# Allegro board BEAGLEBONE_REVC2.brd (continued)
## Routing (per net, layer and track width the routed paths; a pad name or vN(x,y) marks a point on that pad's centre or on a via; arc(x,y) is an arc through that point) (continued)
PHY_VDDCR: length 4.3
  TOP w0.254: U15.6 26.79,29.33 27.16,28.96 v1(27.18,28.96)
  BOTTOM w0.381: C125.1 28.13,30.54 C124.1 28.07,29.84 v1(27.18,28.96)
PHY_XTAL1: length 6.9
  TOP w0.121: Y4.1 26.29,26.54 v1(26.29,27.81)
  BOTTOM w0.121: R140.2 25.75,25.53 25.88,25.65 25.88,26.42 26,26.54 C132.1 ; C132.1 26.7,26.54 26.83,26.42 26.83,25.65 26.96,25.53 R199.1 ; C132.1 26.29,26.61 v1(26.29,27.81)
PHY_XTAL2: length 4.8
  TOP w0.121: U15.4 25.78,29.21 25.85,29.14 25.85,28.77 25.4,28.32 v1(25.4,27.81)
  BOTTOM w0.121: v1(25.4,27.81) R140.1 R144.1
PHYX: length 5.1
  TOP w0.121: Y4.2 23.18,26.48 v1(23.18,27.81)
  BOTTOM w0.121: R144.2 23.75,25.53 23.62,25.65 23.62,26.42 23.5,26.54 C131.1 v1(23.18,27.81)
PLLFILT: length 2.6
  TOP w0.121: C145.1 16.95,40.32 17.91,41.27 U11.25
PMIC_INT: length 17.7
  TOP w0.121: v1(40.51,27.05) 41.02,27.05 42.26,28.29 U5.B18
  LYR3 w0.133: v1(29.21,23.81) 29.72,24.32 29.72,25.02 29.97,25.27 34.42,25.27 v1(34.92,24.77) 35.18,24.77 35.69,25.27 37.97,25.27 38.61,25.91 39.12,25.91 40.26,27.05 v1(40.51,27.05)
  BOTTOM w0.121: R28.2 v1(34.92,24.77) ; v1(29.21,23.81) R10.2
PMIC_INT_PU: length 4.6
  TOP w0.121: v1(34.92,27.3) 34.51,27.72 33.66,27.72 33.53,27.59 33.53,26.41 33.66,26.28 U14.7
  BOTTOM w0.121: R28.1 v1(34.92,27.3)
PMIC_INT_SRC: length 17.5
  TOP w0.121: 30.61,26.29 29.69,25.37 29.69,21.68 v1(30.16,21.21) ; 30.61,26.29 31.54,26.29 U14.2 ; 30.61,26.29 30.61,26.67 30.72,26.78 U14.1 ; U2.45 24.4,20.08 24.51,20.19 24.51,20.83 v1(24.38,20.95)
  LYR3 w0.133: v1(24.38,20.95) 25.15,21.72 29.65,21.72 v1(30.16,21.21)
  BOTTOM w0.121: R10.1 R203.2 v1(30.16,21.21)
PMIC_PGOOD: length 35
  TOP w0.121: v1(44.73,27.89) U5.B15 ; v1(29.72,13.46) 29.1,14.08 29.1,14.57 28.96,14.71 U2.26
  LYR3 w0.121: v1(44.73,27.89) 44.33,27.49 43.76,27.49
  LYR3 w0.133: v1(29.21,24.77) 29.21,25.15 29.59,25.53 37.72,25.53 38.35,26.16 38.81,26.16 40.13,27.49 42.15,27.49 42.16,27.5 42.5,27.5 42.5,27.49 43.76,27.49
  LYR4 w0.133: v1(29.72,13.46) 30.63,14.38 30.63,24.99 30.35,25.27 29.72,25.27 v1(29.21,24.77)
  BOTTOM w0.121: v1(29.21,24.77) R20.1 C25.1
PMIC_POWR_EN: length 48.1
  TOP w0.121: v1(19.18,15.75) 21.13,15.75 21.37,15.51 U2.9 ; v1(52.73,28.69) U5.C6
  LYR3 w0.133: v1(19.18,15.75) 20.7,17.27 27.94,17.27 28.57,16.64 31.11,16.64 35.56,21.08 39.62,21.08 39.88,21.34 43.94,21.34 44.2,21.08 52.58,21.08 v1(52.7,21.21)
  LYR4 w0.133: v1(52.7,21.21) 52.32,21.59 52.32,28.28 v1(52.73,28.69)
PWR_BUT: length 13.8
  TOP w0.121: v1(29.72,12.64) 28.47,13.88 U2.25
  LYR4 w0.133: P9.9 28.7,3.05 28.7,11.62 v1(29.72,12.64)
PWR_LED: length 21.2
  TOP w0.121: v1(21.46,20.32) 22.33,19.46 U2.1
  BOTTOM w0.121: R6.1 5.4,17.34 5.84,17.78 17.78,17.78 18.8,18.8 18.8,20.32 19.3,20.83 20.95,20.83 v1(21.46,20.32)
PWR_LEDR: length 4
  TOP w0.121: v1(5.59,15.56) D1.2 4.64,17.02 TP14.1
  BOTTOM w0.121: R6.2 5.27,16.32 5.59,16 v1(5.59,15.56)
RBIAS: length 2.7
  TOP w0.121: v1(22.23,29.53) 22.86,30.16 22.86,30.48 23.01,30.63 U15.32
  BOTTOM w0.121: v1(22.23,29.53) 21.46,29.53
RCLKIN: length 9
  TOP w0.121: U15.5 26.29,29.21 26.29,29.21 v1(26.29,28.96) 26.71,28.54 27.35,28.54 27.39,28.57 v1(29.21,28.57)
  BOTTOM w0.121: R199.2 27.3,27.94 v1(26.29,28.96) ; v1(29.21,28.57) 29.69,29.05 30.45,29.05 R200.2
REFCLKO: length 5.2
  TOP w0.121: R209.2 v1(30.1,28.57) 29.59,29.08 27.69,29.08 27.29,29.48 U15.7
  BOTTOM w0.121: R209.2 v1(30.1,28.57)
REMU_RSTN: length 61.5
  TOP w0.121: U16.1 31.1,42.56 30.86,42.8 v1(30.86,43.18)
  LYR3 w0.133: v1(36.2,13.97) 38.86,13.97 40.01,15.11 v1(52.32,15.11)
  LYR4 w0.133: v1(30.86,43.18) 33.02,41.02 33.02,39.12 32.77,38.86 32.77,37.08 32,36.32 32,28.57 32.64,27.94 34.04,27.94 34.42,27.56 34.42,27.05 35.81,25.65 35.81,21.46 35.05,20.7 35.05,15.11 v1(36.2,13.97)
  BOTTOM w0.121: v1(52.32,15.11) 53.47,13.97 54.99,13.97 55.12,14.1 R172.2 58.55,14.61 59.82,15.88 R182.1
RESETN: length 3.8
  TOP w0.121: U11.17 21.46,44.57 22.23,45.34 22.23,45.85 20.95,45.85
RMII1_COL: length 23.4
  TOP w0.121: v1(43.93,32.69) U5.H16 ; R207.1 32.07,35.24 v1(32.64,35.81)
  LYR3 w0.133: v1(43.93,32.69) 43.47,33.15 39.75,33.15 39.62,33.27 38.48,33.27 v1(37.97,32.77)
  BOTTOM w0.121: v1(32.64,35.81) 30.83,35.81 30.61,35.59 30.61,35.28 30.83,35.05 34.29,35.05 34.54,35.31 34.54,36.07 34.8,36.32 35.43,36.32 36.2,35.56 36.2,33.02 36.96,32.26 36.96,31.88 37.21,31.62 37.72,31.62 37.97,31.88 v1(37.97,32.77)
RMII1_CRS_DV: length 23.1
  TOP w0.121: v1(33.66,32.38) 33.66,33.02 32.89,33.78 32.45,33.78 R139.1 ; v1(36.45,32) 36.45,33.02 36.7,33.27 41.31,33.27 41.53,33.49 43.13,33.49 U5.H17
  LYR3 w0.133: v1(33.66,32.38) 34.54,32.38 35.18,33.02 35.69,33.02 35.81,32.89 35.81,32 35.69,31.88 34.29,31.88 34.16,31.75 34.16,31.37 34.29,31.24 37.97,31.24 38.1,31.37 38.1,31.88 37.97,32 v1(36.45,32)
RMII1_REFCLK: length 20.8
  TOP w0.121: R201.2 37.21,31.37 v1(37.21,30.48) ; R209.1 v1(32.64,28.57)
  LYR3 w0.133: v1(37.21,30.48) 36.58,29.84 33.78,29.84 33.66,29.72 33.66,29.46 33.78,29.34 36.58,29.34 36.7,29.21 36.7,28.96 36.58,28.83 34.29,28.83 34.16,28.7 34.16,28.45 34.29,28.32 36.58,28.32 36.7,28.19 36.7,27.94 36.58,27.81 33.4,27.81 v1(32.64,28.57)
  BOTTOM w0.121: v1(32.64,28.57) 32.64,28.83 R200.1
RMII1_RXCLK: length 20.2
  TOP w0.121: v1(37.97,35.81) 38.73,35.81 39.24,36.32 40.77,36.32 41.64,35.45 42.69,35.45 U5.L18
  LYR4 w0.133: v1(33.66,28.57) 34.8,29.72 34.8,35.18 34.92,35.31 35.18,35.31 35.31,35.18 35.31,34.16 35.43,34.04 35.81,34.04 35.94,34.16 35.94,35.18 36.07,35.31 37.47,35.31 v1(37.97,35.81)
  BOTTOM w0.121: R136.1 32.38,28.13 33.21,28.13 v1(33.66,28.57)
RMII1_RXD0: length 23.3
  TOP w0.121: U5.M16 43.93,36.69 v1(43.13,36.69) ; v1(33.66,35.81) 33.15,35.31 33.15,34.04 34.29,32.89 34.29,32.13 34.04,31.88 32.45,31.88 R135.1
  LYR3 w0.133: v1(43.13,36.69) 42.72,37.1 41.91,37.1 41.78,36.97 41.78,36.45 41.66,36.32 38.73,36.32 38.61,36.45 38.61,36.7 38.73,36.83 39.88,36.83 40.01,36.96 40.01,37.21 39.88,37.34 36.07,37.34 35.94,37.21 35.94,36.45 35.81,36.32 34.16,36.32 v1(33.66,35.81)
RMII1_RXD1: length 23.3
  TOP w0.121: U5.L15 v1(44.73,35.09) ; R132.1 32.83,31.43 33.27,30.99 33.91,30.99 34.16,30.73 34.16,28.83 34.29,28.7 34.54,28.7 34.67,28.83 34.67,33.91 34.29,34.29 v1(33.66,34.29)
  LYR3 w0.121: 43.56,34.69 44.09,34.69 44.49,35.09 v1(44.73,35.09)
  LYR3 w0.133: 43.56,34.69 43.55,34.7 34.06,34.7 v1(33.66,34.29)
RMII1_RXD2: length 23.4
  TOP w0.121: R153.1 v1(32.64,30.48) ; v1(44.73,35.89) U5.L16
  LYR4 w0.133: v1(32.64,30.48) 33.15,30.99 33.15,38.35 33.27,38.48 36.32,38.48 v1(37.97,36.83)
  BOTTOM w0.121: v1(44.73,35.89) U5.L16 43.76,35.49 43.18,34.91 43.18,34.67 42.93,34.42 41.02,34.42 39.12,36.32 38.48,36.32 v1(37.97,36.83)
RMII1_RXD3: length 23.1
  TOP w0.121: U5.L17 43.53,35.49 43.13,35.09 41.4,35.09 41.19,35.31 37.72,35.31 v1(37.21,35.81) ; R205.1 v1(32.64,29.53)
  LYR4 w0.133: v1(37.21,35.81) 36.07,35.81 35.94,35.94 35.94,37.34 35.81,37.47 35.43,37.47 35.31,37.34 35.31,36.45 35.18,36.32 34.92,36.32 34.8,36.45 34.8,37.34 34.67,37.47 34.29,37.47 34.16,37.34 34.16,30.1 33.59,29.53 v1(32.64,29.53)
RMII1_RXDV: length 26.4
  TOP w0.121: R208.1 20.45,35.56 20.7,35.81 v1(21.34,35.81) ; U5.J17 v1(43.93,34.29)
  LYR3 w0.133: v1(30.1,35.81) 31.11,34.8 32.77,34.8 33.15,34.42 33.15,34.16 33.53,33.78 34.04,33.78 34.29,34.04 40.01,34.04 40.16,33.88 42.77,33.88 43.18,34.29 v1(43.93,34.29)
  LYR4 w0.133: v1(21.34,35.81) 21.84,36.32 29.59,36.32 v1(30.1,35.81)
RMII1_RXERR: length 23.3
  TOP w0.121: v1(44.73,34.29) U5.J15 ; R137.1 v1(32.64,33.34)
  LYR3 w0.121: v1(44.73,34.29) 44.33,33.89 43.54,33.89
  LYR3 w0.133: v1(32.64,33.34) 30.92,33.34 30.48,33.78 29.08,33.78 28.83,34.04 28.83,34.8 29.08,35.05 30.23,35.05 31.5,33.78 33.02,33.78 33.4,33.4 34.16,33.4 34.54,33.78 39.88,33.78 40.01,33.65 43.3,33.65 43.54,33.89
RMII1_TXCLK: length 23.4
  TOP w0.121: R206.1 31.94,37.02 v1(31.75,37.21) ; v1(35.18,37.97) 35.18,37.21 37.44,34.95 41.01,34.95 41.27,34.69 U5.K18
  LYR3 w0.133: v1(31.75,37.21) 31.11,37.21 30.99,37.08 30.99,36.7 31.11,36.58 35.43,36.58 35.56,36.7 35.56,36.96 35.43,37.08 32.38,37.08 32.26,37.21 32.26,37.44 32.38,37.57 34.77,37.57 v1(35.18,37.97)
RMII1_TXD0: length 28
  TOP w0.121: v1(25.02,35.81) 25.28,35.55 U15.22 ; U5.K17 43.13,34.29 41.15,34.29 40.73,34.71 37.3,34.71 34.42,37.59 v1(34.42,37.97)
  LYR3 w0.133: v1(34.42,37.97) 33.78,38.61 23.37,38.61 23.11,38.35 23.11,36.58 23.24,36.45 24.89,36.45 25.02,36.32 v1(25.02,35.81)
RMII1_TXD1: length 28.7
  TOP w0.121: v1(24.26,35.81) 24.38,35.81 24.78,35.41 U15.23 ; v1(43.93,35.09) U5.K16
  LYR3 w0.133: v1(24.26,35.81) 24.26,35.05 24.38,34.92 25.34,34.92 25.46,35.05 25.46,36.96 25.34,37.08 24.26,37.08 24.13,37.21 24.13,37.72 24.26,37.85 26.42,37.85 27.69,36.58 29.97,36.58 31.5,35.05 43.89,35.05 v1(43.93,35.09)
RMII1_TXD2: length 29.1
  TOP w0.121: U15.24 24.28,35.15 23.81,35.62 23.81,36 24.13,36.32 26.29,36.32 26.48,36.51 29.97,36.51 30.1,36.64 v1(30.1,37.21) ; v1(45.53,35.09) U5.K15
  LYR3 w0.121: 43.62,35.49 45.13,35.49 45.53,35.09 v1(45.53,35.09)
  LYR3 w0.133: v1(30.1,37.21) 30.1,36.83 31.62,35.31 38.35,35.31 38.48,35.43 38.48,35.81 38.61,35.94 38.86,35.94 38.99,35.81 38.99,35.43 39.12,35.31 39.37,35.31 39.5,35.43 39.5,35.81 39.62,35.94 39.88,35.94 40.01,35.81 40.01,35.43 40.13,35.31 41.02,35.31 41.15,35.43 41.15,35.81 41.27,35.94 41.53,35.94 41.66,35.81 41.66,35.43 41.78,35.31 42.04,35.31 42.16,35.43 42.16,35.56 42.29,35.69 42.55,35.69 42.67,35.56 42.67,35.43 42.8,35.31 43.43,35.31 43.62,35.49
RMII1_TXD3: length 28.4
  TOP w0.121: U5.J18 41.15,33.89 41.04,33.78 39.88,33.78 39.37,34.29 37.34,34.29 v1(33.66,37.97) ; U15.25 23.24,34.14 22.92,34.45 22.92,36 23.24,36.32 23.5,36.32 24.51,37.34 27.48,37.34 27.56,37.26 27.56,37.16 27.48,37.08 26.11,37.08 26.04,37.01 26.04,36.84 26.11,36.77 28.89,36.77 v1(29.34,37.21)
  LYR3 w0.133: v1(29.34,37.21) 30.1,37.97 v1(33.66,37.97)
RMII1_TXEN: length 29
  TOP w0.121: U15.21 25.78,35.69 v1(25.91,35.81) ; v1(43.93,33.49) U5.J16
  LYR3 w0.133: v1(43.93,33.49) 43.82,33.38 39.85,33.38 39.72,33.51 34.78,33.51 34.16,32.89 27.3,32.89 26.42,33.78 23.11,33.78 22.99,33.91 22.99,34.29 23.11,34.42 26.42,34.42 26.54,34.54 26.54,34.8 26.42,34.92 26.04,34.92 25.91,35.05 v1(25.91,35.81)
RSVD3: length 2.6
  TOP w0.121: 23.5,45.85 23.5,45.34 22.46,44.3 U11.15
RTC_PORZ: length 30
  TOP w0.121: U5.B5 v1(53.53,27.89)
  LYR3 w0.133: v1(31.11,23.81) 33.34,23.81 33.91,23.24 35.81,23.24 36.73,24.16 38.89,24.16 39.5,24.77 52.45,24.77 53.53,25.84 v1(53.53,27.89)
  BOTTOM w0.121: 31.59,25.53 31.59,24.29 v1(31.11,23.81) R143.2 ; 31.59,25.53 R141.1 ; 31.59,25.53 R18.1
RTCK: length 2.8
  BOTTOM w0.121: R178.2 P7.9
RXD0/MODE0: length 8.4
  TOP w0.121: R135.2 v1(30.1,32.38) 30.1,32.13 29.6,31.63 U15.11
  LYR3 w0.133: v1(32.64,32.38) v1(30.1,32.38)
  BOTTOM w0.121: R198.1 33.91,32.89 33.15,32.89 v1(32.64,32.38) ; v1(30.1,32.38) R135.2
RXD1/MODE1: length 7.6
  TOP w0.121: U15.10 29.8,31.13 v1(30.1,31.43) R132.2
  LYR3 w0.133: v1(33.66,31.43) v1(30.1,31.43)
  BOTTOM w0.121: R5.1 v1(33.66,31.43) ; v1(30.1,31.43) R132.2
RXD2/RMIISEL: length 7.2
  TOP w0.121: U15.9 29.06,30.63 29.21,30.48 v1(30.1,30.48) R153.2 31.4,30 33.18,30 v1(33.66,30.48)
  BOTTOM w0.121: R153.2 v1(30.1,30.48) ; R212.1 v1(33.66,30.48)
RXD3/PHYAD2: length 10.4
  TOP w0.121: U15.8 27.79,29.46 27.91,29.34 29.91,29.34 v1(30.1,29.53) R205.2
  BOTTOM w0.121: R213.1 35.43,28.92 35.31,29.05 34.54,29.05 34.42,29.18 R214.1 33.94,30 30.26,30 30.1,29.84 v1(30.1,29.53)
RXDV: length 2.9
  TOP w0.121: U15.26 23.13,33.64 22.67,34.1 22.67,34.48 22.1,35.05 21.46,35.05
RXER/PHYAD0: length 7.6
  TOP w0.121: R137.2 v1(30.1,33.34) 30.1,33.02 29.97,32.89 29.47,32.89 29.21,32.64 U15.13
  BOTTOM w0.121: R126.2 33.21,33.34 32.73,33.81 31.4,33.81 R137.2 v1(30.1,33.34)
RXN: length 20.3
  TOP w0.095: P10.2 17.14,33.97 17.02,34.1 16.13,34.1 16,33.97 16,32.53 16.52,32 17.78,32 18.52,32.74 18.52,33.39 19.19,34.06 20.18,34.06 21.08,33.16 21.08,31.62 21.61,31.1 21.89,31.1 v1(22.23,31.43) 22.29,31.5 22.85,31.5 22.99,31.63 U15.30
  BOTTOM w0.095: 21.46,31.43 v1(22.23,31.43)
  BOTTOM w0.121: P10.2 C127.1
RXP: length 17.8
  TOP w0.095: U15.31 22.97,31.13 22.89,31.22 22.63,31.22 22.48,31.06 22.48,30.73 v1(22.23,30.48) 21.89,30.82 21.49,30.82 20.8,31.51 20.8,33.05 20.07,33.78 19.3,33.78 18.8,33.27 18.8,32.62 17.9,31.72 16.41,31.72 15.72,32.41 15.72,34.06 15.49,34.29 P10.1
  BOTTOM w0.095: 21.46,30.48 v1(22.23,30.48)
  BOTTOM w0.121: P10.1 C126.1
SD_CD: length 14.8
  LYR3 w0.133: v1(71.63,24.64) 72.14,25.15 72.39,25.15 v1(73.91,26.67)
  BOTTOM w0.121: R197.1 R196.1 70.99,22.23 71.63,22.86 v1(71.63,24.64) ; v1(73.91,26.67) 73.15,27.43 73.15,30.73 71.97,31.92 P4.11
SPI1_CS0: length 27.9
  TOP w0.121: v1(47.13,28.69) U5.C12
  LYR4 w0.133: v1(47.13,28.69) 47.13,28.18 48.01,27.3 48.01,22.99 47.12,22.1 47.12,21.72 49.15,19.68 49.15,17.4 51.05,15.49 51.05,7.62 52.7,5.97 P9.28
SPI1_D0: length 31.7
  TOP w0.121: 55.24,1.91 53.98,3.17 53.98,5.21 53.34,5.84 51.82,5.84 v1(50.67,6.99) ; v1(46.33,27.89) U5.B13
  LYR4 w0.133: v1(46.33,27.89) 46.99,27.23 46.99,23.5 46.35,22.86 46.35,22.1 48.9,19.56 48.9,17.27 50.67,15.49 v1(50.67,6.99)
SPI1_D1: length 29.9
  TOP w0.121: v1(47.13,29.49) U5.D12
  LYR4 w0.121: v1(47.13,29.49) 47.53,29.09 47.53,28.42
  LYR4 w0.133: 55.24,4.45 55.24,5.71 53.34,7.62 52.32,7.62 51.44,8.51 51.44,15.49 49.4,17.53 49.4,19.81 48.13,21.08 48.13,22.23 48.51,22.61 48.51,27.43 47.53,28.42
SPI1_SCLK: length 33.4
  TOP w0.121: v1(46.33,27.09) U5.A13
  LYR4 w0.133: v1(46.33,27.09) 46.33,26.54 46.08,26.29 46.08,22 48.64,19.43 48.64,10.54 49.28,9.91 49.28,7.49 v1(49.78,6.99)
  BOTTOM w0.121: P9.31 56.64,3.05 52.07,3.05 51.44,3.68 51.44,5.33 v1(49.78,6.99)
SYS_5V: length 134.5
  TOP w0.203: 21.59,16.13 21.81,15.91 U2.8 ; 21.59,16.13 v1(21.46,16.13) ; 21.59,16.13 21.77,16.31 U2.7
  TOP w0.381: v1(14.42,45.85) 13.14,45.85 FB4.2
  TOP w0.508: C133.1 69.87,14.63 75.27,14.63 v1(75.57,14.93)
  LYR3 w0.508: 27.3,5.71 67.94,5.71 74.8,12.57 74.8,14.16 v1(75.57,14.93)
  LYR3 w0.762: P9.8 27.3,5.71 23.11,9.91 19.68,9.91 v1(18.8,10.79)
  LYR4 w0.381: v1(14.42,45.85) 13.14,45.85 11.43,44.13 11.43,41.4 14.99,37.85 17.91,37.85 20.32,35.43 20.32,22.86 19.05,21.59 19.05,19.56 20.32,18.29 20.32,16.13
  LYR4 w0.762: v1(21.46,16.13) 20.32,16.13 20.32,14.73 18.8,13.21 v1(18.8,11.56) v1(18.8,10.79)
  BOTTOM w0.381: v1(18.8,10.79) v1(18.8,11.56) 18.29,11.56 18.03,11.3 18.03,10.79 ; v1(18.8,10.79) 18.03,10.79 ; v1(18.8,10.79) 18.8,10.16 R3.2 18.03,10.16 18.03,10.79 ; U9.2 75.89,14.28 75.56,14.61 75.56,14.92 v1(75.57,14.93) U9.3 ; v1(14.42,45.85) 18.41,45.85
  BOTTOM w0.762: P9.7 P9.8
SYS_RESETN: length 81.4
  TOP w0.121: U15.19 v1(26.79,35.81) ; U5.A10 49.13,27.03 48.76,26.66 48.76,26.03 46.86,24.13 v1(46.86,22.61) ; v1(10.29,41.59) 10.16,41.47 R23.2 R27.1
  LYR3 w0.133: v1(31.11,20.45) 31.6,20.93 31.6,21.47 31.85,21.72 32.26,21.72 32.77,21.21 34.04,21.21 34.54,21.72 36.7,21.72 37.08,21.34 39.5,21.34 40.41,22.25 43.54,22.25 44.45,21.34 45.59,21.34 v1(46.86,22.61) ; v1(22.23,35.81) 21.08,36.96 14.61,36.96 11.81,39.75 11.07,39.75 10.69,40.13 10.69,41.19 v1(10.29,41.59)
  LYR4 w0.133: v1(22.23,35.81) 22.73,35.31 26.28,35.31 v1(26.79,35.81) 27.94,34.66 27.94,28.96 28.96,27.94 29.21,27.94 31.6,25.55 31.6,20.93 v1(31.11,20.45) 31.11,13.08 29.84,11.81 P9.10
SYS_VOLT: length 57.2
  TOP w0.203: U2.32 29.17,17.11 29.34,17.27 v1(29.46,17.27) ; U2.2 21.82,18.31 v1(21.46,18.67) ; U2.21 26.4,12.77 26.67,12.5 v1(26.67,12.45) 26.8,12.58 U2.22 ; U2.39 v1(26.8,20.32) ; v1(25.62,20.32) 25.6,20.3 U2.42
  TOP w0.381: v1(18.8,6.99) v1(18.03,6.99) 18.03,9.65 17.5,10.18 U8.8 16.76,10.23 v1(16.76,10.79)
  LYR3 w0.635: 26.8,18.8 26.8,18.8 v1(26.8,20.32) ; v1(25.62,20.32) 25.62,18.8
  LYR3 w0.762: v1(21.46,18.67) 21.59,18.8 28.57,18.8 29.46,17.91 v1(29.46,17.27) ; v1(18.03,6.99) v1(18.8,6.99) 21.87,6.99 v1(22.86,5.97)
  LYR4 w0.762: v1(22.86,5.97) 22.86,7.75 26.67,11.56 v1(26.67,12.45) 28.45,14.22 28.45,16.26 v1(29.46,17.27)
  BOTTOM w0.381: v1(16.76,10.79) 17.02,10.54 17.02,10.03 ; C17.2 24.45,20 24.77,20.32 v1(25.62,20.32) ; C9.2 C8.2 26.35,12.76 v1(26.67,12.45) ; v1(29.46,17.27) 28.51,17.27 C10.2 ; R2.2 v1(22.86,5.97) ; v1(26.8,20.32) 26.8,19.75 C18.2 ; v1(21.46,18.67) 21.46,18.03 21.59,17.91 22.1,17.91 C19.2 ; v1(18.8,6.99) 18.8,7.62 18.41,8 18.03,7.62 v1(18.03,6.99) v1(18.8,6.99)
SYS_WARMRESETN: length 33.1
  TOP w0.121: S1.2 5.51,40.72 5.78,40.45 C101.1 R27.2 8.26,39.91 8.48,39.69 10.48,39.69 v1(11.11,40.32)
  LYR3 w0.133: v1(11.11,40.32) 11.75,40.32 14.73,37.34 21.08,37.34 23.11,39.37 28.07,39.37 29.72,41.02 29.72,41.27 v1(29.08,41.91)
  BOTTOM w0.121: v1(29.08,41.91) 29.21,42.04 29.84,42.04 30.23,42.42 R163.2
TCK: length 2.8
  BOTTOM w0.121: R180.2 64.29,13.34
TCT_RCT: length 6.4
  BOTTOM w0.121: C130.1 R142.1 P10.5 15.88,29.21 P10.4
TDIS: length 8.8
  BOTTOM w0.121: 69.7,8.26 67.18,8.26 66.55,8.89 62.74,8.89 62.1,8.26 R177.1
TESTOUT: length 2.6
  TOP w0.121: TP6.1 54.58,25.43 54.58,27.34 U5.A3
TIMER4: length 30.2
  TOP w0.121: v1(51.93,39.09) U5.R7
  LYR3 w0.121: v1(51.93,39.09) 51.53,39.49 51.53,40.29
  LYR3 w0.133: 51.53,40.29 44.45,47.37 41.02,47.37 40.13,48.26 31.24,48.26 30.73,48.77 28.7,48.77 P8.7
TIMER5: length 27.7
  TOP w0.121: v1(52.73,39.89) U5.T6
  LYR3 w0.133: P8.9 30.73,49.28 31.24,49.28 31.75,48.77 43.85,48.77 v1(52.73,39.89)
TIMER6: length 30.2
  TOP w0.121: v1(50.49,44.01) 50.86,44.01 51.28,43.59 51.41,43.59 51.69,43.31 51.69,42.55 52.73,41.5 52.73,40.69 U5.U6
  LYR3 w0.133: P8.10 31.11,51.44 31.11,49.91 32,49.02 43.92,49.02 43.94,49 43.95,49 48.95,44.01 v1(50.49,44.01)
TIMER7: length 31.7
  TOP w0.121: v1(51.93,39.89) U5.T7
  LYR3 w0.133: P8.8 28.57,51.44 28.57,49.78 29.34,49.02 30.99,49.02 31.5,48.51 40.26,48.51 41.15,47.62 44.58,47.62 51.93,40.27 v1(51.93,39.89)
TXCLK: length 5.8
  TOP w0.121: R206.2 30.86,36.26 26.64,36.26 26.37,35.99 26.37,35.56 26.29,35.48 U15.20
TXN: length 22.8
  TOP w0.095: v1(22.23,33.34) 22.23,32.96 22.55,32.64 U15.28
  LYR3 w0.102: P10.6 17.14,28.96 16.38,29.72 16.03,29.72 15.9,29.59 15.9,27.41 16.46,26.85 18.21,26.85 21.08,29.72 21.08,32.51 21.51,32.94 21.83,32.94 v1(22.23,33.34)
  BOTTOM w0.095: 21.46,33.34 v1(22.23,33.34)
  BOTTOM w0.121: P10.6 C129.1
TXP: length 20.3
  TOP w0.095: U15.29 22.99,32.13 22.77,32.36 22.24,32.36 22.22,32.37 v1(22.22,32.38)
  LYR3 w0.102: v1(22.23,32.38) 21.97,32.64 21.64,32.64 21.39,32.39 21.39,29.59 18.34,26.54 16.33,26.54 15.6,27.28 15.6,30.76 P10.3
  BOTTOM w0.095: 21.46,32.38 v1(22.23,32.38)
  BOTTOM w0.121: C128.1 P10.3
U5_H18: length 5
  TOP w0.121: R201.1 39.37,31.5 40.01,32.13 41.02,32.13 41.98,33.09 U5.H18
UART0_CTS: length 20.1
  TOP w0.121: U5.E17 43.13,30.29 42.1,30.29 40.91,29.1 39.89,29.1 39.24,28.45 38.86,28.45 38.48,28.07 38.48,24.51 39.75,23.24 39.75,22.1 40.87,20.98 44.29,20.98 45.33,19.94 U12.40
UART0_RTS: length 19.5
  TOP w0.121: U5.E18 41.87,30.69 41.15,29.97 40.36,29.97 39.08,28.7 38.73,28.7 38.23,28.19 38.23,24.38 39.5,23.11 39.5,21.97 40.73,20.74 44.03,20.74 44.84,19.93 U12.41
UART0_RX: length 15.8
  TOP w0.121: v1(45.34,17.65) 45.59,17.65 45.84,17.9 U12.39 ; v1(43.93,30.29) U5.E16
  LYR4 w0.133: v1(43.93,30.29) 43.44,29.8 43.44,21.58 44.45,20.57 44.45,19.56 45.34,18.67 v1(45.34,17.65)
UART0_TX: length 19.1
  TOP w0.121: v1(44.73,30.29) U5.E15 ; U12.38 46.33,17.9 45.34,16.91 v1(45.34,16.89)
  LYR4 w0.121: 43.56,30.61 43.64,30.69 44.33,30.69 v1(44.73,30.29)
  LYR4 w0.133: 43.56,30.61 43.21,30.25 43.21,21.47 44.2,20.48 44.2,19.3 44.83,18.67 44.83,17.4 v1(45.34,16.89)
UART1_RXD: length 32.1
  TOP w0.121: v1(43.93,29.49) U5.D16
  LYR4 w0.121: v1(43.93,29.49) 44.33,29.09 44.33,26.8
  LYR4 w0.133: 44.33,26.8 44.32,26.8 44.32,23.75 43.69,23.11 43.69,21.69 44.7,20.67 44.7,19.81 45.85,18.67 45.85,5.97 46.61,5.21 46.61,3.81 47.12,3.3 49.02,3.3 P9.26
UART1_TXD: length 27.9
  TOP w0.121: v1(44.73,29.49) U5.D15
  LYR4 w0.121: v1(44.73,29.49) 45.13,29.09 45.13,28.45
  LYR4 w0.133: P9.24 47.62,6.73 46.1,8.26 46.1,18.92 44.96,20.07 44.96,20.75 43.94,21.77 43.94,22.61 44.83,23.5 44.83,26.54 45.21,26.92 45.21,28.37 45.13,28.45
UART2_RXD: length 26.5
  TOP w0.121: U5.A17 40.64,24.6 40.64,22.51 40.89,22.26 41.62,22.26 v1(42.04,21.84)
  LYR4 w0.133: P9.22 45.09,7.37 43.69,8.76 43.69,20.2 43.16,20.73 43.15,20.73 v1(42.04,21.84)
UART2_TXD: length 31.5
  TOP w0.121: U5.B17 43.13,27.89 42.42,27.89 41.66,27.12 41.66,26.13 40.39,24.86 40.39,22.23 40.77,21.84 v1(41.4,21.84)
  LYR4 w0.133: v1(41.4,21.84) 42.55,20.69 42.55,18.66 43.43,17.78 43.43,14.99 42.77,14.33 42.77,9.04 44.7,7.11 44.7,5.71 44.07,5.08 44.07,2.92 P9.21
UART3_CTSN: length 28.9
  TOP w0.121: 53.34,45.85 v1(53.34,45.09) 55.13,43.3 55.13,40.69 U5.U3
  LYR3 w0.133: v1(53.34,45.09) 55.24,46.99 65.41,46.99 65.66,47.24 65.66,47.63 65.41,47.88 65.4,47.88 64.26,49.02 62.48,49.02 61.85,49.66 61.85,51.69 P8.36
  BOTTOM w0.121: 53.34,45.85 v1(53.34,45.09)
UART3_RTSN: length 29.8
  TOP w0.121: 51.44,45.85 v1(51.44,45.09) 51.85,44.67 52.74,44.67 53.59,43.81 53.59,42.67 54.33,41.94 54.33,40.69 U5.U4
  LYR3 w0.133: P8.34 59.31,51.69 59.31,49.15 59.44,49.02 60.45,49.02 60.58,48.9 60.58,48.64 60.45,48.51 49.15,48.51 49.02,48.39 49.02,47.5 v1(51.44,45.09)
  BOTTOM w0.121: 51.44,45.85 v1(51.44,45.09)
UART4_CTSN: length 29.8
  TOP w0.121: U5.V2 55.53,43.85 v1(54.29,45.09) 54.29,45.85
  LYR3 w0.133: v1(54.29,45.09) 54.29,45.15 55.88,46.74 67.44,46.74 67.69,46.99 67.69,47.95 67.44,48.2 65.47,48.2 64.14,49.53 64.14,51.31 63.88,51.56 63.12,51.56 62.87,51.31 P8.35
  BOTTOM w0.121: 54.29,45.85 v1(54.29,45.09)
UART4_RTSN: length 29.5
  TOP w0.121: 52.39,45.85 v1(52.39,45.09) 52.7,45.09 53.85,43.94 53.85,42.83 54.73,41.95 U5.V3
  LYR3 w0.133: v1(52.39,45.09) 50.04,47.43 50.04,48.01 50.16,48.13 64.01,48.13 64.14,48.26 64.14,48.51 64.01,48.64 61.85,48.64 P8.33
  BOTTOM w0.121: 52.39,45.85 v1(52.39,45.09)
UART4_RXD: length 53.9
  TOP w0.121: v1(32.51,40.01) 33.02,40.51 35.18,40.51 36.03,39.66 40.13,39.66 40.36,39.89 43.13,39.89 U5.T17
  LYR4 w0.133: P9.11 33.66,3.17 33.66,5.21 33.91,5.46 33.91,10.54 34.67,11.3 34.67,20.83 34.42,21.08 34.42,22.61 35.43,23.62 35.43,25.53 34.16,26.8 33.27,26.8 31.62,28.45 31.62,36.45 32.51,37.34 v1(32.51,40.01)
UART4_TXD: length 49.1
  TOP w0.121: U5.U17 43.13,40.69 42.37,40.69 42.19,40.51 40.26,40.51 39.9,40.15 38.59,40.15 v1(38.1,40.64)
  LYR4 w0.133: v1(38.1,40.64) 38.1,38.86 38.86,38.1 38.86,35.31 35.94,32.38 35.94,26.54 36.32,26.16 36.32,21.08 35.69,20.45 35.69,16.13 36.2,15.62 36.58,15.62 37.97,14.22 37.97,7.24 36.07,5.33 36.07,3.05 P9.13
UART5_CTSN: length 29.2
  TOP w0.121: 50.48,45.85 v1(50.48,45.09) 50.99,44.58 51.56,44.58 51.71,44.42 52.61,44.42 53.34,43.69 53.34,42.55 53.93,41.95 U5.V4
  LYR3 w0.133: P8.31 57.78,51.31 58.04,51.56 58.67,51.56 58.93,51.31 58.93,49.28 58.67,49.02 47.5,49.02 47.24,48.77 47.24,48.32 v1(50.48,45.09)
  BOTTOM w0.121: 50.48,45.85 v1(50.48,45.09)
UART5_RTSN: length 29.6
  TOP w0.121: v1(53.53,39.89) U5.T5 ; 49.53,45.85 v1(49.53,45.09)
  LYR3 w0.133: v1(49.53,45.09) 46.48,48.13 46.48,50.8 47.37,51.69 56.77,51.69 P8.32
  BOTTOM w0.121: v1(53.53,39.89) 53.53,43.88 52.83,44.58 50.04,44.58 v1(49.53,45.09) 49.53,45.85
UART5_RXD: length 29.3
  TOP w0.121: 55.24,45.85 v1(55.24,45.09) 55.88,44.45 55.88,41.45 55.93,41.4 55.93,40.69 U5.U2
  LYR3 w0.133: v1(55.24,45.09) 56.64,46.48 67.69,46.48 67.94,46.74 67.94,48.26 67.69,48.51 65.53,48.51 64.39,49.66 64.39,51.69 P8.38
  BOTTOM w0.121: 55.24,45.85 v1(55.24,45.09)
UART5_TXD: length 29.3
  TOP w0.121: U5.U1 56.83,40.79 56.83,44.45 v1(56.2,45.09) 56.2,45.85
  LYR3 w0.133: v1(56.2,45.09) 57.34,46.23 65.02,46.23 65.93,45.32 67.94,45.32 68.2,45.57 68.2,48.51 67.94,48.77 66.8,48.77 66.55,49.02 66.55,51.31 66.29,51.56 65.66,51.56 65.41,51.31 P8.37
  BOTTOM w0.121: 56.2,45.85 v1(56.2,45.09)
USB0_DM: length 25.6
  TOP w0.114: U5.N18 42.61,37.21 41.43,37.21 40.54,38.1 36.05,38.1 35.7,38.46 23.61,38.46 22.21,37.06 20.59,37.06 20.18,37.48 20.18,37.9 20.1,37.97 19.89,37.97 19.81,38.05 19.81,38.16 19.96,38.3 U11.2
USB0_DP: length 25.7
  TOP w0.114: U5.N17 43.13,37.49 41.55,37.49 40.66,38.38 36.17,38.38 35.81,38.73 23.5,38.73 22.1,37.34 20.71,37.34 20.45,37.59 U11.3
USB0_ID: length 12
  TOP w0.121: v1(39.75,39.24) 38.23,39.24 37.72,38.73 36.45,38.73 35.56,39.62 TP4.1 ; U5.P16 v1(43.93,38.29)
  BOTTOM w0.121: v1(43.93,38.29) 43.43,38.79 43.43,39.11 42.79,39.75 40.26,39.75 v1(39.75,39.24)
USB0_VBUS: length 37.8
  TOP w0.121: v1(36.07,41.91) 35.42,41.26 U16.4 ; v1(44.73,38.29) U5.P15
  LYR3 w0.133: v1(36.07,41.91) 34.16,43.81 25.91,43.81 22.86,46.86 v1(17.53,46.86)
  BOTTOM w0.121: R152.2 v1(17.53,46.86) ; v1(36.07,41.91) 36.07,42.67 36.7,43.31 42.8,43.31 43.94,42.16 43.94,40.64 44.33,40.25 44.33,38.69 v1(44.73,38.29)
USB0_VBUS_PWR: length 9.2
  TOP w0.121: U16.3 31.24,41.26 31.1,41.4 28.57,41.4 27.81,40.64 25.15,40.64 24.51,41.27 U11.11
USB1_DM: length 65.4
  TOP w0.114: U5.R18 42.61,38.81 42.12,38.81 41.91,38.59 v1(41.91,38.35)
  LYR3 w0.127: v1(78.11,17.14) 77.9,17.14 76.59,15.83 P2.2 72.52,16.68 65.58,16.68 64.54,15.64 42.78,15.64 42.52,15.9 42.52,16.49 v1(42.93,16.89)
  LYR4 w0.127: v1(41.91,38.35) 41.91,38.1 41.27,37.47 41.27,24.64 40.41,23.78 40.41,21.82 41.4,20.83 41.4,17.53 42.04,16.89 v1(42.93,16.89)
  BOTTOM w0.114: U10.2 78.58,18.41 78.36,18.19 77.96,18.19 77.71,17.94 77.71,17.54 v1(78.11,17.14)
USB1_DP: length 65.5
  TOP w0.114: U5.R17 43.13,39.09 42.01,39.09 v1(41.27,38.35)
  LYR3 w0.127: v1(78.11,17.78) 76.46,16.14 74.67,16.14 74.17,16.64 74.17,17.04 P2.3 72.52,16.99 65.45,16.99 64.41,15.95 43.11,15.95 v1(42.93,16.13)
  LYR4 w0.127: v1(42.93,16.13) 42.55,16.51 41.99,16.51 41.1,17.4 41.1,20.7 40.11,21.69 40.11,23.9 40.97,24.76 40.97,37.59 41.27,37.9 v1(41.27,38.35)
  BOTTOM w0.114: v1(78.11,17.78) 78.24,17.92 U10.1
USB1_DRVVBUS: length 44.9
  TOP w0.121: U5.F15 v1(44.73,31.09)
  LYR4 w0.121: v1(44.73,31.09) 45.13,30.69 45.13,30.12 45.36,29.89 45.93,29.89 v1(46.33,29.49)
  BOTTOM w0.121: U9.4 77.06,16.92 76.83,17.14 R147.1 76.2,17.91 74.93,19.18 69.98,19.18 68.33,20.83 65.53,20.83 64.52,21.84 58.93,21.84 58.55,21.46 54.48,21.46 52.32,23.62 46.74,23.62 46.08,24.28 46.08,26.14 46.73,26.79 46.73,29.09 v1(46.33,29.49)
USB1_ID: length 1.9
  TOP w0.121: v1(43.13,38.29) 43.18,38.24 U5.P17
  BOTTOM w0.121: R146.1 42.93,39.09 43.13,38.89 v1(43.13,38.29)
USB1_OC: length 72.3
  TOP w0.121: v1(43.93,39.89) U5.T16
  LYR3 w0.133: v1(83.19,17.14) 82.3,18.03 79.76,18.03 78.74,19.05 67.06,19.05 66.17,18.16 61.09,18.16 59.94,17.02 54.61,17.02 54.1,16.51 50.04,16.51 48.39,18.16 43.43,18.16 v1(42.93,17.65)
  LYR4 w0.133: v1(42.93,17.65) 42.32,18.26 42.32,20.57 41.99,20.9 41.71,20.9 40.65,21.96 40.65,23.5 41.55,24.4 41.55,27.83 41.66,27.94 41.66,37.34 42.32,38 42.32,38.89 43.32,39.89 v1(43.93,39.89)
  BOTTOM w0.121: U9.5 82.89,15.58 83.19,15.88 v1(83.19,17.14) R148.2
USB1_VBUS: length 83.9
  TOP w0.381: U5.T18 40.76,39.49 v1(40.52,39.25)
  TOP w0.635: v1(81.92,17.14) 83.18,15.88 v1(83.18,14.93)
  LYR3 w0.381: P2.1 55.75,13.34 55.12,12.7 42.8,12.7 v1(41.91,13.59)
  LYR4 w0.381: v1(41.91,13.59) 41.91,14.1 40.39,15.62 40.39,19.56 39.88,20.07 39.88,20.96 39.52,21.31 39.52,27.96 39.94,28.38 39.94,38.67 v1(40.52,39.25)
  BOTTOM w0.305: U10.6 81.91,17.92 C134.1
  BOTTOM w0.381: 83.18,14.28 U9.7 ; 83.18,13.63 U9.8 ; U9.6 v1(83.18,14.93) ; C134.1 v1(81.92,17.14)
  BOTTOM w0.635: P2.1 74.26,12.45 82.68,12.45 83.18,12.95 v1(83.18,14.93)
USB_DC: length 54.2
  TOP w0.121: U2.12 22.33,13.72 21.82,13.21 v1(21.46,13.21)
  LYR4 w0.133: v1(12.06,43.18) 12.06,41.4 15.11,38.35 18.16,38.35 20.7,35.81 20.7,21.27 21.02,20.95 21.02,17.84 22.23,16.64 22.23,13.97 v1(21.46,13.21)
  BOTTOM w0.121: R149.1 19.3,46.86 19.05,46.61 19.05,45.21 18.67,44.83 12.83,44.83 12.06,44.07 v1(12.06,43.18) 11.73,42.85 P3.1 ; C2.1 21.72,13.46 v1(21.46,13.21)
USBDM_DN: length 12.3
  TOP w0.114: U11.21 18.81,43.68 18.26,44.22 10.48,44.22 v1(9.91,43.65)
  BOTTOM w0.114: P3.2 v1(9.91,43.65)
USBDP_UP: length 12.3
  TOP w0.114: v1(10.67,43.65) 10.96,43.94 18.15,43.94 18.55,43.53 U11.22
  BOTTOM w0.114: P3.3 8.89,44.45 9.27,44.07 10.25,44.07 v1(10.67,43.65)
USR0: length 21.1
  TOP w0.121: U5.V15 45.13,41.36 44.45,42.04 41.53,42.04 40.77,42.8 40.51,42.8 39.62,43.69 36.64,43.69 35.18,45.15 35.18,46.74 33.66,48.26 33.27,48.26 33.02,48.01 33.02,46.48 32.89,46.35 Q1.2 31.62,46.35 31.37,46.1 v1(31.37,45.72)
  BOTTOM w0.121: v1(31.37,45.72) R116.1
USR1: length 17
  TOP w0.121: Q1.5 34.42,46.35 34.67,46.1 v1(34.67,45.72) 34.67,45.02 36.26,43.43 39.5,43.43 40.39,42.55 40.64,42.55 41.4,41.78 44.2,41.78 44.49,41.49 44.5,41.49 44.73,41.26 44.73,40.69 U5.U15
  BOTTOM w0.121: v1(34.67,45.72) 34.67,46.61 34.29,46.99 R117.1
USR2: length 23.2
  TOP w0.121: v1(27.56,45.72) 27.56,46.1 27.81,46.35 Q2.2 ; v1(44.73,39.89) U5.T15
  LYR3 w0.133: v1(27.56,45.72) 30.23,45.72 31.75,44.2 34.54,44.2 37.08,41.66 39.37,41.66 40.01,41.02 41.15,41.02 41.78,41.66 42.96,41.66 v1(44.73,39.89)
  BOTTOM w0.121: v1(27.56,45.72) R118.1
USR3: length 22.4
  TOP w0.121: v1(30.86,46.99) 30.86,46.61 30.61,46.35 Q2.5 29.34,46.35 29.21,46.23 29.21,44.83 29.59,44.45 34.61,44.45 35.88,43.18 39.37,43.18 40.01,42.55 40.01,41.4 40.26,41.15 41.27,41.15 41.66,41.53 43.89,41.53 U5.V16
  BOTTOM w0.121: v1(30.86,46.99) R119.1
VDCDC1: length 1.1
  TOP w0.203: v1(25.4,12.45) 25.6,12.65 U2.19
VDCDC3: length 8
  TOP w0.203: U2.29 29.3,15.91 v1(29.46,15.75)
  BOTTOM w0.508: v1(36.2,16.26) 29.97,16.26 v1(29.46,15.75)
VPP: length 0.6
  TOP w0.305: v1(53.53,36.69) U5.M5
VREFP_ADC: length 7.1
  TOP w0.121: 49.53,27.89 49.53,26.92 49.4,26.8
  TOP w0.305: U5.B9 49.53,27.89 ; 49.4,26.8 49.1,26.5 49.1,25.63 48.55,25.07 R78.2 48.58,24.73
  TOP w0.381: C30.1 C29.1 ; C29.1 C28.1 ; C29.1 48.58,24.73
VRTC: length 50.7
  TOP w0.203: U2.3 21.21,17.91
  TOP w0.254: 32.51,23.29 v1(33.02,23.29) U17.8 34.49,23.63 34.67,23.81 v1(34.92,23.81) ; 32.51,23.29 U17.1 ; 32.51,23.29 32.51,22.99 32.32,22.79 U17.2
  TOP w0.305: v1(51.93,29.49) U5.D7
  TOP w0.381: 21.21,17.91 19.82,17.91 v1(19.68,17.78)
  LYR3 w0.381: v1(53.09,26.16) v1(51.12,26.16) 50.1,25.14 39.11,25.14 38.61,24.64 36.45,24.64 35.62,23.81 v1(34.92,23.81) ; v1(19.68,17.78) 19.05,18.41 19.05,20.83 20.83,22.61 31.75,22.61 32.44,23.29 v1(33.02,23.29)
  BOTTOM w0.152: R77.1 53.61,24.26 53.48,24.38 53.48,25.77 v1(53.09,26.16)
  BOTTOM w0.381: C20.1 v1(19.68,17.78) ; v1(51.12,26.16) C98.1 ; C21.1 v1(34.92,23.81)
VRTC_DET: length 2.7
  TOP w0.121: v1(33.03,22.61) 33.21,22.79 U17.7
  BOTTOM w0.121: R17.1 32.58,23.05 33.02,22.61 v1(33.03,22.61)
VRTC_DET_OUT: length 3.2
  TOP w0.121: U17.3 30.73,22.29 30.61,22.17 30.61,21.34 30.73,21.21 v1(31.11,21.21)
  BOTTOM w0.121: R143.1 v1(31.11,21.21)
VRTC_DETB: length 5.3
  TOP w0.121: U17.6 33.52,22.29 v1(33.02,21.79) U17.5
  BOTTOM w0.121: C22.1 33.26,22.03 v1(33.02,21.79) 32.78,22.03 R17.2
WAKEUP: length 51.5
  TOP w0.121: U5.C5 v1(53.53,28.69)
  LYR3 w0.133: v1(55.88,21.91) 54.78,20.8 44.09,20.8 43.81,21.08 40.01,21.08 39.73,20.8 35.66,20.8 31.11,16.26 29.34,16.26 28.83,15.75 28.83,13.21 v1(28.07,12.45)
  LYR4 w0.133: v1(53.53,28.69) 55.88,26.34 v1(55.88,21.91)
  BOTTOM w0.121: R11.2 24.38,14.48 24.77,14.1 24.77,13.65 26.47,11.94 27.56,11.94 v1(28.07,12.45) ; v1(53.53,28.69) 53.53,28.45 53.37,28.29 53.36,28.29 53.13,28.05 53.13,26.75 53.98,25.91 R77.2
WP: length 13.3
  BOTTOM w0.121: R210.2 31.5,8.89 31.24,8.64 29.97,8.64 29.78,8.45 U7.7 28.45,8 28.19,7.75 28.19,6.22 28.45,5.97 33.91,5.97 TP2.1
XDMA_EVENT_INTR0: length 25.2
  TOP w0.121: v1(44.73,27.09) U5.A15
  BOTTOM w0.121: v1(44.73,27.09) 44.73,26.7 43.94,25.91 43.94,23.62 44.45,23.11 52.07,23.11 54.22,20.97 58.79,20.97 59.56,20.19 59.56,17.4 59.82,17.14 R183.1
XTALIN: length 7.4
  TOP w0.121: 15.37,41.75 R160.1 ; 15.37,41.75 C137.2 v1(13.34,41.27) ; 15.37,41.75 18.55,41.75 U11.24
  BOTTOM w0.121: Y5.3 14.29,41.27 v1(13.34,41.27)
XTALOUT: length 5.1
  TOP w0.121: v1(17.14,43.18) C144.2 R160.2 16.43,42.27 U11.23
  BOTTOM w0.121: v1(17.14,43.18) 16.19,43.18 Y5.1
XTIN: length 10.6
  TOP w0.121: U12.2 41.84,9.13 v1(42.23,9.53)
  BOTTOM w0.121: C153.2 37.47,12.57 37.72,12.83 40.77,12.83 41.11,12.48 Y6.3 41.83,11.38 42.04,11.18 42.04,9.72 v1(42.23,9.53)
XTOUT: length 8.9
  TOP w0.121: U12.3 42.33,6.46 v1(42.23,6.35)
  BOTTOM w0.121: Y6.1 38.66,7.43 C155.2 37.47,6.48 37.85,6.1 41.97,6.1 v1(42.23,6.35)
YEL_C: length 3.5
  BOTTOM w0.121: R16.2 3.81,27.94 3.35,27.48 P10.11
N21360640: length 5.5
  TOP w0.121: U15.18 27.29,35.41 v1(27.69,35.81)
  BOTTOM w0.121: v1(27.69,35.81) 28.19,36.32 28.32,36.32 28.89,36.89 28.89,37.53 29.97,38.61 R220.1

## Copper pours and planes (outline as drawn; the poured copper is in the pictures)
DGND on TOP (solid shape): 16,7.56 14.48,7.56 14.48,10.86 16,10.86
DGND on TOP (solid shape): 81.28,12.7 77.47,12.7 77.47,16.51 81.28,16.51
DGND on BOTTOM (solid shape): 16.26,10.41 16.26,8.38 16,8.13 14.48,8.13 14.22,8.38 14.22,10.41 14.48,10.67 16,10.67
DGND on TOP: 21.21,24.64 21.21,28.07 21.46,28.32 28.07,28.32 28.32,28.07 28.32,24.64 28.07,24.38 21.46,24.38
DGND on BOTTOM: 37.08,6.35 36.83,6.6 36.83,6.8 36.88,6.99 36.83,7.17 36.83,12.32 37.08,12.57 41.66,12.57 41.91,12.32 41.91,6.6 41.66,6.35
DGND on BOTTOM: 12.83,40.39 12.83,44.07 13.08,44.32 17.4,44.32 17.65,44.07 17.65,40.39 17.4,40.13 13.08,40.13
DGND on BOTTOM: 45.09,35.56 45.21,35.69 45.21,36.07 45.72,36.07 45.72,35.69 45.97,35.43 45.97,34.8 45.72,34.54 45.72,34.16 45.09,34.16
DGND on LYR2_GND: 10.16,3.49 12.7,6.03 16.51,6.03 18.1,4.45 18.1,1.91 18.73,1.27 73.98,1.27 75.27,1.51 76.52,1.91 77.15,2.54 77.15,8.26 76.52,8.89 74.61,8.89 73.98,9.53 73.98,11.11 74.61,11.75 83.5,11.75 84.14,12.38 84.14,21.27 83.5,21.91 74.61,21.91 73.98,22.54 73.98,24.13 74.61,24.77 83.5,24.77 84.14,25.4 84.14,44.13 83.5,44.77 77.47,44.77 77.15,45.09 77.15,52.07 76.52,52.7 75.13,53.22 73.66,53.34 18.73,53.34 18.1,52.7 18.1,50.16 16.51,48.58 12.7,48.58 12.06,49.21 2.22,49.21 1.59,48.58 1.59,40.32 2.22,39.69 11.75,39.69 12.7,38.73 12.7,36.83 12.06,36.2 10.48,36.2 9.21,37.47 2.54,37.47 1.91,36.83 1.91,31.43 2.54,30.8 2.54,28.89 1.91,28.26 1.91,22.86 2.54,22.23 9.21,22.23 10.48,23.5 12.06,23.5 12.7,22.86 12.7,20.95 11.75,20 2.54,20 1.91,19.37 1.91,5.4 3.81,3.49
GND_OSC0 on BOTTOM: 37.97,43.81 47.12,43.81 47.37,44.07 47.37,48.64 47.12,48.9 37.97,48.9 37.72,48.64 37.72,44.07
GND_OSC1 on TOP: 53.66,20.19 53.66,12.45 59.37,12.45 59.37,20.19
VDD_1V8 on BOTTOM: 42.42,27.69 43.18,27.69 43.43,27.94 43.43,28.7 43.69,28.96 45.09,28.96 45.34,29.21 45.34,29.59 45.47,29.72 45.72,29.72 45.85,29.84 45.85,30.48 45.72,30.61 45.09,30.61 44.32,31.37 43.43,31.37 43.18,31.11 43.18,30.35 42.93,30.1 42.29,30.1 42.29,27.81
VDD_1V8 on BOTTOM: 19.3,11.18 19.3,13.21 19.56,13.46 20.7,13.46 21.72,12.45 21.72,9.53 22.1,9.14 22.1,7.75 21.59,7.75 21.59,8.89 21.21,9.27 19.81,9.27 19.81,10.67
VDD_1V8 on BOTTOM: 52.32,25.15 52.32,27.81 52.58,28.07 52.58,30.23 52.32,30.48 51.56,30.48 51.31,30.23 51.31,26.29 51.82,25.78 51.82,25.15
VDD_1V8 on BOTTOM: 51.69,40.57 51.37,40.89 51.37,41.53 50.89,41.53 50.89,40.89 50.55,40.55 50.55,38.99 50.16,38.61 50.16,38.23 50.29,38.1 51.05,38.1 51.69,38.73
VDD_1V8 on LYR3: 45.72,39.62 45.97,39.37 45.97,38.1 45.72,37.85 45.09,37.85 44.58,37.34 41.4,37.34 40.89,37.85 36.58,37.85 36.32,38.1 36.32,40.01 36.58,40.26 43.05,40.26 43.69,39.62
VDD_1V8 on LYR4: 52.45,30.1 52.2,29.84 51.69,29.84 51.44,30.1 51.44,30.48 51.31,30.61 49.91,30.61 49.28,29.97 45.47,29.97 45.21,30.23 45.21,33.53 44.96,33.78 43.81,33.78 43.56,34.04 43.56,39.37 43.81,39.62 52.2,39.62 52.45,39.37
VDD_1V8 on LYR5_PWR: 49.85,31.43 49.53,31.11 49.53,30.8 49.21,30.48 48.58,30.48 48.58,17.78 48.9,17.46 53.98,17.46 54.29,17.78 54.29,25.34 52.9,26.73 52.9,31.11 52.58,31.43
VDD_3V3A on BOTTOM: 46.1,41.53 46.1,40.89 45.72,40.51 45.72,38.35 45.97,38.1 47.12,38.1 47.24,38.23 47.24,38.35 46.86,38.73 46.86,40.64 46.57,40.93 46.57,41.53
VDD_3V3A on BOTTOM: 43.69,34.8 44.2,34.8 44.58,34.42 44.58,34.16 44.83,33.91 45.47,33.91 45.72,33.66 45.72,32.64 45.21,32.64 45.21,33.02 44.83,33.4 44.32,33.4 44.07,33.66 42.42,33.66 42.42,34.16 43.05,34.16
VDD_3V3A on BOTTOM: 51.94,38.1 53.85,38.1 54.1,38.35 54.1,40.26 54.57,40.72 54.57,41.53 54.1,41.53 54.1,40.89 53.72,40.51 53.72,38.99 53.34,38.99 53.34,40.51 52.96,40.89 52.96,41.53 52.5,41.53 52.5,40.94 52.07,40.51 52.07,38.73 51.82,38.48 51.82,38.23
VDD_3V3A on LYR5_PWR: 38.42,12.7 38.42,14.92 38.73,15.24 43.18,15.24 43.5,15.56 43.5,19.68 43.81,20 47.94,20 48.26,20.32 48.26,30.48 48.58,30.8 48.9,30.8 49.21,31.11 49.21,31.43 49.53,31.75 52.64,31.75 52.9,32 52.9,36.13 53.21,36.45 53.59,36.45 53.78,36.64 53.78,38.67 54.17,39.05 55.24,39.05 55.69,39.5 55.69,41.08 58.1,43.5 80.01,43.5 80.33,43.18 80.33,25.08 80.64,24.77 83.5,24.77 84.14,25.4 84.14,44.13 83.5,44.77 77.47,44.77 77.15,45.09 77.15,52.07 76.52,52.7 75.13,53.22 73.66,53.34 18.73,53.34 18.1,52.7 18.1,50.16 16.51,48.58 12.7,48.58 12.06,49.21 2.22,49.21 1.59,48.58 1.59,40.32 2.22,39.69 11.11,39.69 11.43,40.01 11.43,45.72 11.75,46.04 17.14,46.04 17.46,46.35 17.46,47.94 17.78,48.26 26.04,48.26 26.35,47.94 26.35,44.77 26.67,44.45 35.88,44.45 36.2,44.13 36.2,19.37 35.88,19.05 19.37,19.05 19.05,18.73 19.05,12.7 19.37,12.38 38.1,12.38
VDD_3V3B on BOTTOM (solid shape): 27.43,37.21 27.43,36.03 27.42,36.01 27.39,35.96 27.37,35.91 27.36,35.86 27.35,35.81 27.36,35.76 27.37,35.71 27.39,35.67 27.42,35.62 27.43,35.6 27.43,34.29 27.3,34.16 26.29,34.16 26.16,34.29 26.16,35.6 26.18,35.62 26.2,35.66 26.22,35.71 26.23,35.76 26.24,35.81 26.24,35.84 26.46,35.84 26.46,35.79 26.46,35.74 26.48,35.69 26.5,35.64 26.53,35.6 26.57,35.56 26.61,35.53 26.66,35.51 26.71,35.49 26.76,35.48 26.81,35.48 26.86,35.49 26.91,35.51 26.96,35.53 27,35.56 27.04,35.6 27.07,35.64 27.09,35.69 27.11,35.74 27.12,35.79 27.12,35.84 27.11,35.89 27.09,35.94 27.07,35.99 27.04,36.03 27,36.07 26.96,36.1 26.91,36.12 26.86,36.14 26.81,36.14 26.76,36.14 26.71,36.14 26.66,36.12 26.61,36.1 26.57,36.07 26.53,36.03 26.5,35.99 26.48,35.94 26.46,35.89 26.46,35.84 26.24,35.84 26.24,35.85 26.23,35.9 26.21,35.95 26.19,35.99 26.16,36.03 26.16,36.07 26.42,36.32 26.42,37.21 26.54,37.34 27.3,37.34
VDD_3V3B on LYR5_PWR: 10.16,3.49 12.7,6.03 16.51,6.03 18.1,4.45 18.1,1.91 18.73,1.27 73.98,1.27 75.27,1.51 76.52,1.91 77.15,2.54 77.15,8.26 76.52,8.89 74.61,8.89 73.98,9.53 73.98,11.11 74.61,11.75 83.5,11.75 84.14,12.38 84.14,21.27 83.5,21.91 54.86,21.91 54.61,21.65 54.61,17.46 54.29,17.14 48.58,17.14 48.26,17.46 48.26,19.37 47.94,19.68 44.13,19.68 43.81,19.37 43.81,15.24 43.5,14.92 39.05,14.92 38.73,14.61 38.73,12.38 38.42,12.06 19.05,12.06 18.73,12.38 18.73,19.05 19.05,19.37 35.56,19.37 35.88,19.68 35.88,43.81 35.56,44.13 26.35,44.13 26.04,44.45 26.04,47.62 25.72,47.94 18.1,47.94 17.78,47.62 17.78,46.04 17.46,45.72 12.06,45.72 11.75,45.4 11.75,39.69 12.7,38.73 12.7,37.15 13.34,36.51 24.13,36.51 24.77,35.88 24.77,28.57 24.45,28.26 21.27,28.26 18.73,25.72 18.73,24.45 17.46,23.18 13.34,23.18 12.7,22.54 12.7,20.95 11.75,20 2.54,20 1.91,19.37 1.91,5.4 3.81,3.49
VDD_5V on TOP (solid shape): 15.75,14.1 15.75,12.57 15.49,12.32 14.99,12.32 14.73,12.57 14.73,13.08 13.34,13.08 11.94,11.68 11.94,9.14 10.41,9.14 10.41,12.57 12.19,14.35 15.49,14.35
VDD_CORE on BOTTOM: 40.13,28.45 40.13,34.54 39.88,34.8 39.12,34.8 38.86,34.54 38.86,28.45 38.48,28.07 38.48,24 37.85,23.37 37.85,22.35 34.92,19.43 34.92,18.29 34.67,18.03 29.97,18.03 29.97,17.27 30.23,17.02 35.56,17.02 38.16,19.62 38.16,20.38 39.88,22.1 39.88,28.19
VDD_CORE on LYR3: 53.98,38.48 53.98,30.86 53.72,30.61 49.78,30.61 49.53,30.86 49.53,32 49.15,32.38 46.23,32.38 45.97,32.13 45.97,29.21 45.72,28.96 38.73,28.96 38.48,29.21 38.48,33.02 38.73,33.27 44.7,33.27 44.96,33.53 44.96,35.31 44.32,35.31 43.81,35.81 43.81,36.2 44.2,36.58 45.21,36.58 45.59,36.96 47.24,36.96 49.02,38.73 53.72,38.73
VDD_MPU on LYR3: 40.13,26.16 40.39,25.91 49.02,25.91 49.28,26.16 49.28,31.88 49.02,32.13 46.35,32.13 46.23,32 46.23,28.7 44.45,26.92 40.39,26.92 40.13,26.67
VDD_PHYA on LYR5_PWR: 24.45,28.89 24.13,28.57 20.95,28.57 18.41,26.04 18.41,24.77 17.14,23.5 10.48,23.5 9.21,22.23 2.54,22.23 1.91,22.86 1.91,28.26 2.54,28.89 2.54,30.8 1.91,31.43 1.91,36.83 2.54,37.47 9.21,37.47 10.48,36.2 23.81,36.2 24.45,35.56
VDD_PLL on BOTTOM: 42.29,33.15 42.93,33.15 43.05,33.27 44.58,33.27 44.83,33.02 44.83,32.38 44.58,32.13 43.43,32.13 42.93,32.64 42.29,32.64
VDD_PLL on BOTTOM: 47.75,41.53 47.75,40.89 47.37,40.51 47.37,38.61 47.88,38.1 48.01,38.1 48.9,38.99 48.9,39.24 48.51,39.62 48.51,40.51 48.13,40.89 48.13,41.53
VDD_PLL on LYR4: 43.56,33.27 44.7,33.27 44.96,33.02 44.96,32.38 44.7,32.13 42.42,32.13 42.16,32.38 42.16,36.7 42.29,36.83 43.18,36.83 43.31,36.7 43.31,33.53
VDDS_DDR on LYR5_PWR: 58.29,43.18 56.01,40.89 56.01,39.24 55.5,38.73 54.36,38.73 54.1,38.48 54.1,36.45 53.85,36.2 53.47,36.2 53.21,35.94 53.21,27.05 54.61,25.65 54.61,22.48 54.86,22.23 73.66,22.23 73.98,22.54 73.98,24.13 74.61,24.77 79.69,24.77 80.01,25.08 80.01,42.86 79.69,43.18
BAT on LYR3 (solid shape): 6.94,17.96 6.99,17.97 7.03,17.96 7.71,17.27 6.99,16.49 6.26,17.27
DC_IN on TOP: 20.96,14.22 21.76,15.01 21.76,15.2 21.72,15.24 18.03,15.24 17.27,14.48 17.27,13.08 17.02,12.83 16.13,12.83 16.13,12.06 17.78,12.06 18.54,12.83 18.54,13.97 18.79,14.22
P_L1 on TOP: 25.72,12.39 25.72,11.88 25.15,11.3 25.15,9.91 25.02,9.78 23.88,9.78 23.62,9.53 23.62,8.26 23.88,8 25.78,8 26.04,8.26 26.04,11.05 26.29,11.3 26.29,12.45 26.04,12.7
P_L2 on TOP: 27.71,12.42 27.81,12.19 28.04,12.09 28.32,11.81 28.32,9.02 28.07,8.76 27.56,8.76 27.3,9.02 27.3,11.43 27.05,11.68 27.05,12.83 27.15,12.92 27.3,12.92 27.71,12.52
P_L3 on TOP: 31.5,16.38 31.5,16.64 31.24,16.89 29.34,16.89 29.21,16.76 29.08,16.76 28.96,16.64 29.46,16.13 31.24,16.13
RXP on BOTTOM (solid shape): 14.62,34.29 13.89,33.58 13.21,34.25 13.2,34.29 13.21,34.33 13.89,35
VDCDC1 on TOP: 24.77,12.06 25.27,12.57 25.4,12.57 25.53,12.45 25.53,12.06 25.02,11.56 21.46,11.56 21.34,11.43 21.34,8.38 21.08,8.13 20.19,8.13 20.19,12.57 20.7,12.57 20.7,12.32 20.95,12.06
VDCDC2 on TOP: 28.32,13.72 29.46,12.57 29.97,12.57 29.97,12.83 30.1,12.95 30.86,12.95 30.99,12.83 30.99,8.89 30.86,8.76 30.23,8.76 29.97,9.02 29.97,11.43 29.84,11.56 29.34,11.56 28.43,12.47 28.32,12.7 28.09,12.8 27.81,13.08 27.56,13.08 27.56,13.72
VDCDC3 on TOP: 34.42,16.51 34.42,15.49 34.67,15.24 36.83,15.24 37.08,15.49 37.08,16.26 36.58,16.26 36.07,16.76 34.67,16.76
VRTC on LYR3: 52.32,29.72 51.56,29.72 51.31,29.46 51.31,26.54 51.05,26.29 51.05,26.04 52.7,26.04 52.7,26.23 52.77,26.3 52.77,26.35 52.58,26.54 52.58,29.46

Small or netless copper shapes (teardrops, artwork), in the pictures only: 477 on TOP, 299 on BOTTOM, 216 on LYR3, 151 on LYR4, 1 on LYR2_GND, 1 on LYR5_PWR

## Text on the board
BOTTOM: PCB RevC2 | LAYER 6 | SOLDER
Board Geometry/Soldermask Bottom: SMS
Ref Des/Silkscreen Bottom: S/N | BSLK
TOP: LAYER 1 | COMPONENT
Board Geometry/Soldermask Top: SMC
Ref Des/Silkscreen Top: USER LEDS | 2 | 3 | 0 | 1 | RESET | PWR | AM335x | USB Host | USB | Ethernet | microSD Card | TSLK
LYR2_GND: LAYER 2 | GROUND
LYR3: CCO | LAYER 3 | SIGNAL
LYR4: LAYER 4 | SIGNAL
LYR5_PWR: LAYER 5 | POWER
DISPLAY_BOTTOM: SPS
DIMENSION: (OZ) | LAYER 1 - PRIMARY SIDE - SIGNAL | LAYER 2 - GROUND PLANE | LAYER 3 - SIGNAL | LAYER 4 - SIGNAL | LAYER 5 - SPLIT POWER PLANE | LAYER 6 - SECONDARY SIDE - SIGNAL | LAYER# | COPPER WEIGHT | HALF+PLATING | IMPEDANCE CONTROL | +/- 10% | 50ohm SINGLE ENDED | TRACE WIDTH | TRACE WIDTH / SPACE | 90ohm DIFFERENTIAL | 100ohm DIFFERENTIAL | 10. ALL VIAS TO HAVE SOLDERMASK. | 9. PLATED THROUGH SLOT INDICATED WITH MULTIPLE DRILL HITS SHOULD BE | FINISHED AS SMOOTH WALL BY VEDOR. | PROCESS NOTES: | 2. APPLY LPI SOLDERMASK OVER BARE COPPER (SMOBC), | COLOR: BONE OR OFF WHITE. SOLDERMASK SHALL | CONFORM TO IPC-SM-840, CLASS H. CURRENT REV. | 3. SOLDERMASK ARTWORK HAS ZERO (0) OVERSIZED PADS. | FABRICATION VENDOR IS ALLOWED TO ADJUST THE COMPONENT | SOLDERMASK PADS TO MEET THEIR TOOLING REQUIREMENTS. | 4. APPLY LPI SILKSCREEN OR EQUIVALENT PER THE ARTWORK. | COLOR: BLACK. | 1. PLATE ALL EXPOSED AREAS WITH ELECTROLESS | IMMERSION GOLD, NICKEL 150 MICROINCHES THK MIN | GOLD 5-15 MICROINCHES THK MIN. | SUPPLIED IPC-D-356 NETLIST. | FAB NOTES: | 1. ALL DIMENSIONS ARE IN INCHES, UNLESS | OTHERWISE NOTED. | 2. THE PWB SHALL BE FABRICATED TO IPC-6012, | CLASS 2 AND WORKMANSHIP SHALL CONFORM TO | IPC-A-600, CLASS 2. CURRENT REVISIONS. | 3. BOARD MATERIAL SHALL BE 180 Tg/350 Td ISOLA FR-370HR | OR EQUIVALENT, RoHS COMPLIANT AND LEAD FREE | ASSEMBLY CAPABLE.  BOARD MATERIAL SHALL | MEET OR EXCEED IPC-4101B. COLOR: NATURAL. | 4. BOARD MATERIAL & CONSTRUCTION TO BE U.L. | APPROVED AND MARKED ON THE FINISHED BOARD. | 5. MINIMUM COPPER WALL THICKNESS OF PLATED-THRU | HOLES TO BE .001 INCH, WITH A MINIMUM | ANNULAR RING OF .002 INCH. | 6. OVERALL BOARD THICKNESS TO BE .062 +/- 10% | AND APPLIES AFTER ALL LAMINATION AND PLATING | PROCESSES, MEASURED FROM COPPER TO COPPER. | 7. MAX. WARP & TWIST TO BE .0075 INCHES PER INCH. | 8. BOARD MUST BE ELECTRICALLY TESTED USING | 1 | 5.25 | 4.75 | 4.5/6.5 | 5.0/7.0 | 3.75/7.25 | 4.00/8.00 | R.250 2X | LAYER STACK-UP - ALL DIMENSIONS IN INCHES
USER_PART_NUM_TOP: TSLKC
USER_PART_NUM_BOTTOM: BSLKC
DISPLAY_TOP: SPC
DEVICE_TYPE_TOP: DATE | DESIGN ENGR | PROJECT ENGR | ENGR MGR | NEXT ASSEMBLY | APPROVED | CHECKED | DRAFTING | ENGR | NONE | 1 OF 1
User.10: R206 | R207 | R139 | R137 | R135 | R132 | R153 | R205 | R209 | R204 | R188 | R174 | R187 | R201 | R56 | R55 | C65 | C90 | C96 | C92 | C93 | C91 | C39 | C37 | C33 | C60 | C58 | C62 | C47 | R146 | C36 | C73 | C80 | C78 | C81 | C71 | C48 | C49 | C76 | C77 | C79 | C63 | C61 | R127 | R126 | R198 | R5 | R212 | R214 | R213 | R162 | R18 | R141 | R143 | R122 | R125 | R124 | R123 | R211 | C25 | R200 | R136 | R20 | C157 | C10 | R131 | C123 | C125 | C124 | C18 | FB5 | C122 | C121 | C120 | C119 | C17 | C19 | R134 | R133 | R130 | R129 | R145 | R216 | R215 | R173 | R13 | R181 | R109 | R112 | R110 | R113 | R111 | C41 | C35 | R114 | C40 | C64 | C82 | R115 | C43 | C34 | C38 | C88 | C45 | R28 | R17 | R199 | C132 | R140 | R144 | R19 | C131 | R203 | C20 | R10 | R9 | R8 | R15 | R121 | C135 | C5 | C4 | D2 | D3 | D4 | D5 | S1 | USER LEDS | D1 | 2 | 3 | 0 | 1 | RESET | C101 | TP10 | TP11 | TP12 | TP13 | C100 | R96 | R97 | R98 | R99 | FB4 | C144 | R160 | C137 | C145 | TP7 | 10 | 9 | TP15 | 21 | R208 | L1 | 15 | 7 | Y4 | TP8 | R158 | R154 | C146 | Q2 | L2 | TP4 | Q1 | U16 | U14 | U17 | L3 | C51 | C52 | 48 | 18 | R78 | 16 | 33 | 32 | Y1 | V | A | TP3 | TP1 | R69 | R68 | R47 | R46 | R67 | R59 | R72 | R71 | R54 | R53 | R52 | R70 | R25 | R63 | R73 | R64 | R38 | R42 | R34 | R61 | R60 | R36 | C116 | R | C133 | C114 | C115 | C117 | C109 | C110 | C111 | C112 | C113 | C89 | 46 | 45 | TP18 | R194 | R193 | C160 | R192 | C159 | R191 | R195 | R190 | 8 | U10 | U9 | C94 | 20 | R196 | R197 | R184 | C103 | C104 | C105 | C106 | C107 | R120 | C108 | C95 | R75 | R74 | R76 | 19 | R51 | R50 | R49 | R48 | R45 | R44 | R58 | R57 | R40 | R62 | R65 | R29 | R37 | R39 | R30 | R35 | R185 | R183 | R182 | C156 | R180 | R178 | R179 | C154 | R177 | R186 | C24 | C23 | R172 | R171 | R170 | R169 | R168 | R166 | R165 | FB6 | FB7 | Y3 | C46 | Y6 | C53 | C69 | C31 | C54 | C32 | FB1 | Y2 | R117 | R116 | C72 | C102 | C14 | R210 | R163 | C149 | R220 | R119 | R118 | C138 | C140 | C139 | R2 | C2 | C142 | R149 | R189 | R157 | R150 | Y5 | C126 | C127 | C128 | C130 | R142 | C129 | C7 | R128 | R138 | R219 | R16 | C3 | U7 | PWR | TP14 | R27 | R23 | R155 | R159 | C136 | R156 | 22 | 28 | R12 | R161 | 14 | TP2 | TP17 | 49 | 64 | C162 | C163 | C27 | R217 | R24 | R21 | C26 | R202 | C30 | C29 | C67 | C28 | R95 | R94 | R91 | C87 | 17 | R93 | R22 | R90 | TP6 | R92 | R89 | R88 | R87 | TP5 | R86 | R85 | R176 | R79 | R43 | R66 | R84 | R32 | R83 | R31 | R82 | R81 | R80 | C68 | R148 | C134 | R147 | C59 | C118 | R100 | R101 | R102 | R103 | R104 | R105 | R106 | R107 | R26 | R108 | R41 | C66 | R33 | R77 | C70 | C97 | C86 | C75 | FB2 | C98 | C83 | C147 | R164 | C151 | C85 | C164 | C99 | C84 | C42 | R175 | C57 | C56 | C161 | FB3 | R221 | C74 | C152 | R218 | C148 | R167 | C150 | C158 | C44 | FB8 | C21 | C153 | C155 | C22 | C15 | C50 | U13 | R7 | C55 | R4 | C9 | C8 | R11 | R1 | R151 | R14 | C141 | C16 | C143 | C165 | R3 | R152 | C6 | C1 | C166 | R6 | DATE | DESIGN ENGR | PROJECT ENGR | ENGR MGR | NEXT ASSEMBLY | APPROVED | CHECKED | DRAFTING | ENGR | 1 OF 1 | P5 | U1 | U8 | P6 | U11 | U2 | U15 | U5 | U12 | AM335x | U6 | P2 | P8 | P9 | USB Host | P4 | P7 | P3 | USB | Ethernet | P10 | microSD Card | S/N | ASSEMBLY SOLDER SIDE
User.11: NONE
User.24: FIGURE | SIZE | 8.0 | 12.0 | 38.0 | 40.0 | 63.0 | 125.0 | 30.0 | 128.0 | 95.0x40.0 | 120.0x40.0 | 140.0x40.0 | DRILL CHART: TOP to BOTTOM | ALL UNITS ARE IN MILS | TOLERANCE | +3.0/-3.0 | +5.0/-5.0 | PLATED | NON-PLATED | QTY | 799 | 28 | 18 | 102 | 2 | 4 | 1
